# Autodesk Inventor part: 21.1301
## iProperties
Created: 2006-02
Material: Steel, Mild
Description: M8X16 SET SCREW FLAT DIN 913
Document SubType Name: Modeling
Standard: DIN 913
Designer: Andy Moles
Standards Organization: DIN
Language: en-US
Size Designation: M8 x 16
Categories: <MemberInstance><Categories><Category DisplayName="Fasteners" InternalName="e4da775c-781d-43d5-af7c-5136215cf5a6" Mnemonic="FSTN"><Category DisplayName="Bolts"
Density: 7.86 g/cm^3
Mass: 5.61117 g
Surface Area: 5.51599 cm^2
Volume: 0.713889 cm^3
Part Number: 21.1301
Author: Andy Moles
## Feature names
1. Body [Revolution]
2. Slot [Extrusion]
3. Chamfer1
4. Chamfer2
